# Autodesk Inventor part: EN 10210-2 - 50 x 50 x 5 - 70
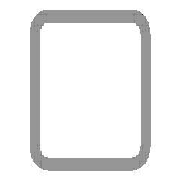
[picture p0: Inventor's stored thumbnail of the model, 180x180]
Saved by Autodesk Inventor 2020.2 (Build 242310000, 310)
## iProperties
IsCustomPart: 1
_CCFamilyMember: 16
_CCFamilyDisplayName: DIN EN 10210-2 (USAS B17.1 quadratisch) - Rohrleitung — In Klammern angegebene Größen wurden aufgehoben
_FrameMemberDoc: Frame Member File
_Version: 15.0.0
_GetPNFromCC: 1
Created: 2019-10
Part Number: EN 10210-2 - 50 x 50 x 5 - 70
Material: Stahl, weich
Description: Rohrleitung
Document SubType Name: Modeling
Standard: DIN
Designer: lutzd
Standard Revision: 2006-07
Standards Organization: DIN
Language: de-DE
Size Designation: 50 x 50 x 5
Categories: <MemberInstance><Categories><Category DisplayName="Profile" InternalName="089c4875-fa83-4c05-b084-43b9cc11f5ed" Mnemonic="GRDR"><CategoryParameter DisplayName="
Stock Number: 50 x 50 x 5
Mass: 479.81 g
Surface Area: 254.441 cm^2
Volume: 61.1222 cm^3
Density: 7.85 g/cm^3
Appearance: Semi-Polished(8)
G_L: 70,000 mm
G_W: 50,000 mm
G_H: 50,000 mm
Dimensions: 50x50x70 mm
Mass: 0,48 kg
DocNumber: ADSK-014290
Folder: .
+1C9B80F7-B6EB-4EDD-A731-AB06723F518C+SCHNITTDETAIL1: Schnittwinkel 90,00 grd
VLT_Material: Stahl, weich
Title: Profil-Bauteil
Author: lutzd
Revision Number: -
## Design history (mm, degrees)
node "Startebene"
node "Endebene"
sketch "Skizze"
  geometry: L1 (-25, -17.5)-(-25, 17.5); L2 (-17.5, 25)-(17.5, 25); L3 (25, 17.5)-(25, -17.5); L4 (17.5, -25)-(-17.5, -25); L5 (-15, 20)-(15, 20); L6 (20, 15)-(20, -15); L7 (15, -20)-(-15, -20); L8 (-20, -15)-(-20, 15); L9 (0, 37.175)-(0, -37.175) reference; L10 (-37.175, 0)-(37.175, 0) reference; A1 r 7.5 centre (-17.5, -17.5) between (-25, -17.5) and (-17.5, -25); A2 r 7.5 centre (-17.5, 17.5) between (-17.5, 25) and (-25, 17.5); A3 r 7.5 centre (17.5, 17.5) between (25, 17.5) and (17.5, 25); A4 r 7.5 centre (17.5, -17.5) between (17.5, -25) and (25, -17.5); A5 r 5 centre (-15, -15) between (-20, -15) and (-15, -20); A6 r 5 centre (-15, 15) between (-15, 20) and (-20, 15); A7 r 5 centre (15, 15) between (20, 15) and (15, 20); A8 r 5 centre (15, -15) between (15, -20) and (20, -15)
  constraints: 16 end point, 16 point on circle, 16 tangent, 8 centre point, 6 equal radius, 4 parallel, 2 perpendicular, 2 other
  dimensions: "d7" = 7.5 radius of A1 (= G_IR); "d10" = 50 distance between parallel lines of L2 L4 (= G_H); "d11" = 50 distance between parallel lines of L1 L3 (= G_W); "d12" = 5 distance between parallel lines of L3 L6 (= G_T); "d15" = 25 distance between parallel lines of L2 L10 (= 0.5 x d10); "d16" = 25 distance between parallel lines of L9 L3 (= 0.5 x d11); "d19" = 5 radius of A5 (= G_T); "d20" = 5 distance between parallel lines of L4 L7 (= G_T)
extrude "Körper" new body sketch "Skizze" stored distance "d3" = 70 (= G_L); taper "d4" = 0 deg
node "Driven Length"
  sketch "Sketch3"
    geometry: L1 (0, 0)-(10, 0) reference
    constraints: 2 end point, 1 horizontal
  workplane "Work Plane3"
  sketch "Sketch4"
    geometry: L1 (-2, 25)-(12, 25) reference; L2 (-2, 95)-(12, 95) reference
    dimensions: "d18" = 70 distance between parallel lines of L1 L2 (derived)
workplane "Arbeitsebene4"
feature "Trennen1"
body "Solid1"
other parameters: "G_W" = 50 [user parameter; used in 1 equation term], "G_H" = 50 [user parameter; used in 1 equation term], "G_T" = 5 [user parameter; used in 3 equation terms], "G_IR" = 7.5 [user parameter; used in 1 equation term], "G_L" = 70 (= d18) [user parameter; used in 1 equation term], "G_OFFSET_START" = -25 [user parameter; used in 1 equation term], "G_OFFSET_END" = 0 [user parameter; used in 1 equation term], "d13" = 25 (= -G_OFFSET_START), "d14" = 95 (= G_OFFSET_END + B_L), "B_L" = 95 [user parameter; used in 1 equation term], "d17" = 90 deg
